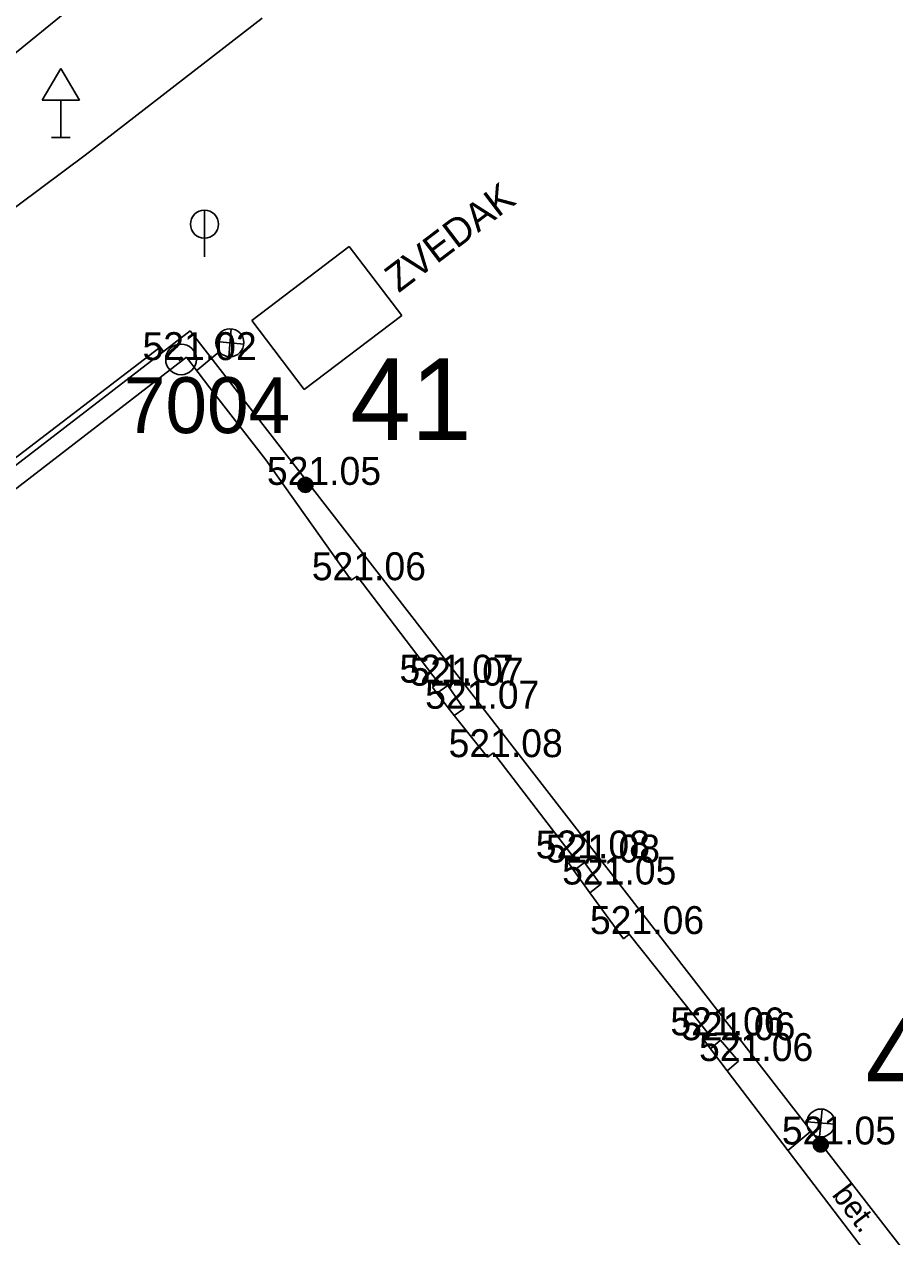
# Model space of a CAD drawing. Extents: x -668867 to -667827, y -1131943 to -1131019.
# Drawn here: x -668502.14 to -668478.76, y -1131318.4 to -1131285.84 of the extents above; entities that cross this region are included whole.
import ezdxf

# ---------------------------------------------------------------- set-up
doc = ezdxf.new("R2010")
doc.units = 0
for name, color, linetype in [('G_Bod_tecka', 7, 'Continuous'), ('G_Bod_vyska', 7, 'Continuous'), ('G_Bodove_pole', 7, 'Continuous'), ('G_Breh_Teren', 7, 'Continuous'), ('G_Budovy_Objekty', 7, 'Continuous'), ('G_Budovy_vstupy', 7, 'Continuous'), ('G_Cesty_Schody', 7, 'Continuous'), ('G_Objekty_dopravni', 7, 'Continuous'), ('G_Objekty_technicke', 7, 'Continuous'), ('G_Plochy_zpevnene', 7, 'Continuous'), ('G_Popisy_povrchu', 7, 'Continuous'), ('G_Poznamky_odkaz', 7, 'Continuous'), ('G_Site-kanalizace', 7, 'Continuous'), ('G_Site-Rozvadece', 7, 'Continuous'), ('G_Site-Sloupy', 7, 'Continuous'), ('Vrstva 1', 7, 'Continuous'), ('Vrstva 4', 7, 'Continuous')]:
    doc.layers.add(name, color=color, linetype=linetype)

msp = doc.modelspace()

# ---------------------------------------------------------------- linework, layer by layer
at = {"layer": 'G_Bod_tecka'}
for p, q in [((-668497.92, -1131294.86), (-668497.92, -1131294.86)), ((-668494.59, -1131298.21), (-668494.59, -1131298.21)), ((-668493.36, -1131300.77), (-668493.36, -1131300.77)), ((-668491.02, -1131303.52), (-668491.02, -1131303.52)), ((-668490.76, -1131303.6), (-668490.76, -1131303.6)), ((-668490.33, -1131304.22), (-668490.33, -1131304.22)), ((-668489.7, -1131305.52), (-668489.7, -1131305.52)), ((-668487.36, -1131308.24), (-668487.36, -1131308.24)), ((-668487.09, -1131308.35), (-668487.09, -1131308.35)), ((-668486.66, -1131308.94), (-668486.66, -1131308.94)), ((-668485.89, -1131310.27), (-668485.89, -1131310.27)), ((-668483.73, -1131312.99), (-668483.73, -1131312.99)), ((-668483.45, -1131313.12), (-668483.45, -1131313.12)), ((-668482.96, -1131313.68), (-668482.96, -1131313.68)), ((-668480.75, -1131315.92), (-668480.75, -1131315.92))]:
    msp.add_line(p, q, dxfattribs=at)
at = {"layer": 'G_Bodove_pole'}
for radius in [0.412, 0.05]:
    msp.add_circle((-668497.93, -1131294.84), radius, dxfattribs=at)
at = {"layer": 'G_Breh_Teren'}
msp.add_line((-668498, -1131283.05), (-668503.25, -1131287.32), dxfattribs=at)
at = {"layer": 'G_Budovy_Objekty'}
for p, q in [((-668493.41, -1131291.81), (-668496.03, -1131293.8)), ((-668493.41, -1131291.81), (-668492, -1131293.66)), ((-668496.03, -1131293.8), (-668494.62, -1131295.65)), ((-668492, -1131293.66), (-668494.62, -1131295.65)), ((-668497.78, -1131294.78), (-668505.94, -1131301.06)), ((-668497.16, -1131295.6), (-668497.78, -1131294.78)), ((-668493.36, -1131300.77), (-668495.65, -1131297.54)), ((-668493.2, -1131300.66), (-668493.36, -1131300.77)), ((-668487.52, -1131308.36), (-668487.36, -1131308.24)), ((-668487.52, -1131308.36), (-668487.38, -1131308.56)), ((-668487.38, -1131308.56), (-668487.09, -1131308.35)), ((-668487.38, -1131308.56), (-668486.95, -1131309.16)), ((-668487.09, -1131308.35), (-668486.66, -1131308.94)), ((-668486.95, -1131309.16), (-668486.66, -1131308.94)), ((-668486.95, -1131309.16), (-668486.05, -1131310.4)), ((-668486.05, -1131310.4), (-668485.89, -1131310.27)), ((-668483.89, -1131313.11), (-668483.73, -1131312.99)), ((-668483.71, -1131313.35), (-668483.89, -1131313.11)), ((-668483.71, -1131313.35), (-668483.44, -1131313.12)), ((-668483.44, -1131313.12), (-668482.96, -1131313.68)), ((-668483.26, -1131313.94), (-668483.71, -1131313.35)), ((-668483.26, -1131313.94), (-668482.96, -1131313.68)), ((-668478.72, -1131319.9), (-668483.26, -1131313.94))]:
    msp.add_line(p, q, dxfattribs=at)
for points in [[(-668491.02, -1131303.52), (-668491.18, -1131303.64)], [(-668491.06, -1131303.8), (-668491.18, -1131303.64)], [(-668491.06, -1131303.8), (-668490.76, -1131303.6)], [(-668490.76, -1131303.6), (-668490.33, -1131304.22)], [(-668490.59, -1131304.4), (-668491.06, -1131303.8)], [(-668490.59, -1131304.4), (-668490.33, -1131304.22)], [(-668489.7, -1131305.52), (-668490.59, -1131304.4)], [(-668489.54, -1131305.4), (-668489.7, -1131305.52)]]:
    msp.add_lwpolyline(points, dxfattribs=at)
at = {"layer": 'G_Budovy_vstupy'}
for p, q in [((-668495.65, -1131297.54), (-668497.16, -1131295.6)), ((-668487.36, -1131308.24), (-668489.54, -1131305.4)), ((-668483.73, -1131312.99), (-668485.89, -1131310.27))]:
    msp.add_line(p, q, dxfattribs=at)
msp.add_lwpolyline([(-668491.02, -1131303.52), (-668493.2, -1131300.66)], dxfattribs=at)
at = {"layer": 'G_Cesty_Schody'}
msp.add_line((-668498.49, -1131294.51), (-668498.4, -1131294.63), dxfattribs=at)
at = {"layer": 'G_Objekty_dopravni'}
for p, q in [((-668501.66, -1131287.881), (-668501.16, -1131287.03)), ((-668501.16, -1131287.03), (-668500.66, -1131287.88)), ((-668501.66, -1131287.881), (-668500.66, -1131287.88)), ((-668501.16, -1131288.88), (-668501.16, -1131287.88)), ((-668501.41, -1131288.88), (-668500.91, -1131288.88))]:
    msp.add_line(p, q, dxfattribs=at)
at = {"layer": 'G_Objekty_technicke'}
for p, q in [((-668496.582, -1131294.021), (-668496.65, -1131294.767)), ((-668496.99, -1131294.36), (-668496.243, -1131294.428)), ((-668497.5, -1131295.13), (-668496.905, -1131294.634)), ((-668480.712, -1131314.97), (-668480.78, -1131315.717)), ((-668481.12, -1131315.309), (-668480.373, -1131315.377)), ((-668481.63, -1131316.08), (-668481.034, -1131315.583))]:
    msp.add_line(p, q, dxfattribs=at)
for centre in [(-668496.616, -1131294.394), (-668480.746, -1131315.343)]:
    msp.add_circle(centre, 0.375, dxfattribs=at)
at = {"layer": 'G_Plochy_zpevnene'}
for p, q in [((-668495.75, -1131285.68), (-668500.5, -1131289.36)), ((-668500.5, -1131289.36), (-668517.1, -1131301.64)), ((-668497.68, -1131294.07), (-668498.4, -1131294.63))]:
    msp.add_line(p, q, dxfattribs=at)
for points in [[(-668460.58, -1131341.88), (-668497.68, -1131294.07)], [(-668498.4, -1131294.63), (-668506.24, -1131300.66), (-668514.54, -1131307.01)]]:
    msp.add_lwpolyline(points, dxfattribs=at)
at = {"layer": 'G_Site-kanalizace'}
msp.add_line((-668497.3, -1131290.835), (-668497.3, -1131292.085), dxfattribs=at)
msp.add_circle((-668497.3, -1131291.21), 0.375, dxfattribs=at)
at = {"layer": 'G_Site-Rozvadece'}
msp.add_line((-668498.49, -1131294.51), (-668527.22, -1131316.48), dxfattribs=at)
at = {"layer": 'G_Site-Sloupy'}
for centre, radius in [((-668494.59, -1131298.21), 0.2), ((-668494.59, -1131298.21), 0.18), ((-668494.59, -1131298.21), 0.16), ((-668494.59, -1131298.21), 0.14), ((-668494.59, -1131298.21), 0.12), ((-668494.59, -1131298.21), 0.1), ((-668494.59, -1131298.21), 0.08), ((-668494.59, -1131298.21), 0.06), ((-668494.59, -1131298.21), 0.04), ((-668494.59, -1131298.21), 0.02), ((-668480.75, -1131315.92), 0.2), ((-668480.75, -1131315.92), 0.18), ((-668480.75, -1131315.92), 0.16), ((-668480.75, -1131315.92), 0.14), ((-668480.75, -1131315.92), 0.12), ((-668480.75, -1131315.92), 0.1), ((-668480.75, -1131315.92), 0.08), ((-668480.75, -1131315.92), 0.06), ((-668480.75, -1131315.92), 0.04), ((-668480.75, -1131315.92), 0.02)]:
    msp.add_circle(centre, radius, dxfattribs=at)
at = {"layer": 'Vrstva 1'}
for p, q in [((-668494.59, -1131298.21), (-668494.59, -1131298.21)), ((-668480.75, -1131315.92), (-668480.75, -1131315.92))]:
    msp.add_line(p, q, dxfattribs=at)

# ---------------------------------------------------------------- texts
at = {"layer": 'G_Bod_vyska'}
for s, p in [('521.02', (-668498.964, -1131294.86)), ('521.05', (-668495.624, -1131298.21)), ('521.06', (-668494.418, -1131300.77)), ('521.07', (-668492.064, -1131303.52)), ('521.07', (-668491.794, -1131303.6)), ('521.07', (-668491.374, -1131304.22)), ('521.08', (-668490.744, -1131305.52)), ('521.08', (-668488.404, -1131308.24)), ('521.08', (-668488.134, -1131308.35)), ('521.05', (-668487.694, -1131308.94)), ('521.06', (-668486.948, -1131310.27)), ('521.06', (-668484.788, -1131312.99)), ('521.06', (-668484.498, -1131313.12)), ('521.06', (-668484.018, -1131313.68)), ('521.05', (-668481.794, -1131315.92))]:
    msp.add_text(s, height=0.75, dxfattribs=at).set_placement(p)
at = {"layer": 'G_Bodove_pole'}
msp.add_text('7004', height=1.5, dxfattribs=at).set_placement((-668499.463, -1131296.82))
at = {"layer": 'G_Popisy_povrchu'}
msp.add_text('bet.', height=0.6, rotation=307.3307, dxfattribs=at).set_placement((-668480.47, -1131317.274))
at = {"layer": 'G_Poznamky_odkaz'}
msp.add_text('ZVEDAK', height=0.75, rotation=37.2215, dxfattribs=at).set_placement((-668492.085, -1131293.068))
at = {"layer": 'Vrstva 4'}
for s, p in [('41', (-668493.387, -1131297.009)), ('43', (-668479.547, -1131314.719))]:
    msp.add_text(s, height=2.1939, dxfattribs=at).set_placement(p)

doc.saveas('drawing.dxf')
